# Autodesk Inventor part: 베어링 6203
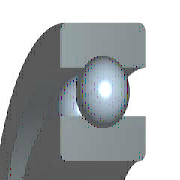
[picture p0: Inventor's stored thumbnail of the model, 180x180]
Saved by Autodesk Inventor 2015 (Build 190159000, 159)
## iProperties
IsCustomPart: 1
Created: 2015-09
Part Number: 베어링 6203
Material: 강철, 연강
Description: 깊은 그루브 볼 베어링
Document SubType Name: Modeling
Standard: KS B 2023
Standards Organization: KS
Language: ko-KR
Size Designation: 6203 - 17 x 40 x 12
Categories: <MemberInstance><Categories><Category DisplayName="샤프트 부품" InternalName="7f7aeb1f-a693-4053-b835-cee3144e0d98" Mnemonic="SHFT"><Category DisplayName="베어링" Inter
Density: 1 g/cm^3
Appearance: 강철
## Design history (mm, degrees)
sketch "스케치" dims "d0" = 5.98 (= -0.26 x WD + 0.26 x BD)
  geometry: L1 (3.01, 14.25)-(8.99, 14.25); L2 (6, 14.25)-(6, 11.26); L3 (6, 14.25)-(6, 17.24); L4 (3.778, 12.249)-(0, 12.249); L5 (0, 8.5)-(12, 8.5); L6 (3.778, 16.251)-(0, 16.251); L7 (0, 20)-(12, 20); L8 (12, 8.5)-(12, 12.249); L9 (8.222, 12.249)-(12, 12.249); L10 (8.222, 16.251)-(12, 16.251); L11 (12, 20)-(12, 16.251); L12 (-1.4, 0)-(8.4, 0) reference; L13 (0, -0.3)-(0, 5.3) reference
  constraints: 22 end point, 4 point on line, 2 collinear, 2 perpendicular, 2 symmetric about line, 1 midpoint, 1 parallel, 14 other
  dimensions: "d9" = 17 diameter of L5 L12 (= WD); "d11" = 40 diameter of L7 L12 (= BD); "d12" = 12 distance between parallel lines of L8 L13 (= KB); "d13" = 24.498 diameter of L9 L12 (= 0.326 x BD + 0.674 x WD)
revolve "본체" stored, may be unused: angle "d6" = 90 deg
revolve "볼" stored, may be unused: angle "d7" = 90 deg
pattern_circular "IDS_ARRAYBALL[SIMPL:T]" dims angle "d3" = 360 deg
body "Solid1"
fillet "모깎기1" dims "d1" = 0.6 (= KRS)
other parameters: "WD" = 17 [user parameter; used in 5 equation terms], "BD" = 40 [user parameter; used in 5 equation terms], "KB" = 12 [user parameter; used in 1 equation term], "KRS" = 0.6 [user parameter; used in 1 equation term], "d4" = 0, "d5" = 0, "d8" = 0, "d14" = 0, "d15" = 0, "BBA" = 0 [user parameter], "BC0" = 4750000 [user parameter], "BC" = 9560000 [user parameter], "WR" = 8.5 (= 0.5 x WD) [user parameter]
